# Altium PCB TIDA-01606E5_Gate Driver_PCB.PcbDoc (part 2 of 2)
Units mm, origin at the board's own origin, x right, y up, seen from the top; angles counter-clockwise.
Board outline 135 x 43 mm, 4 copper layers (Top Layer, GND, PWR, Bottom Layer), stack 1.59 mm thick; 184 components, 90 nets, 537 pads, 139 vias.
Unrouted connection lines stored in the file: 48.
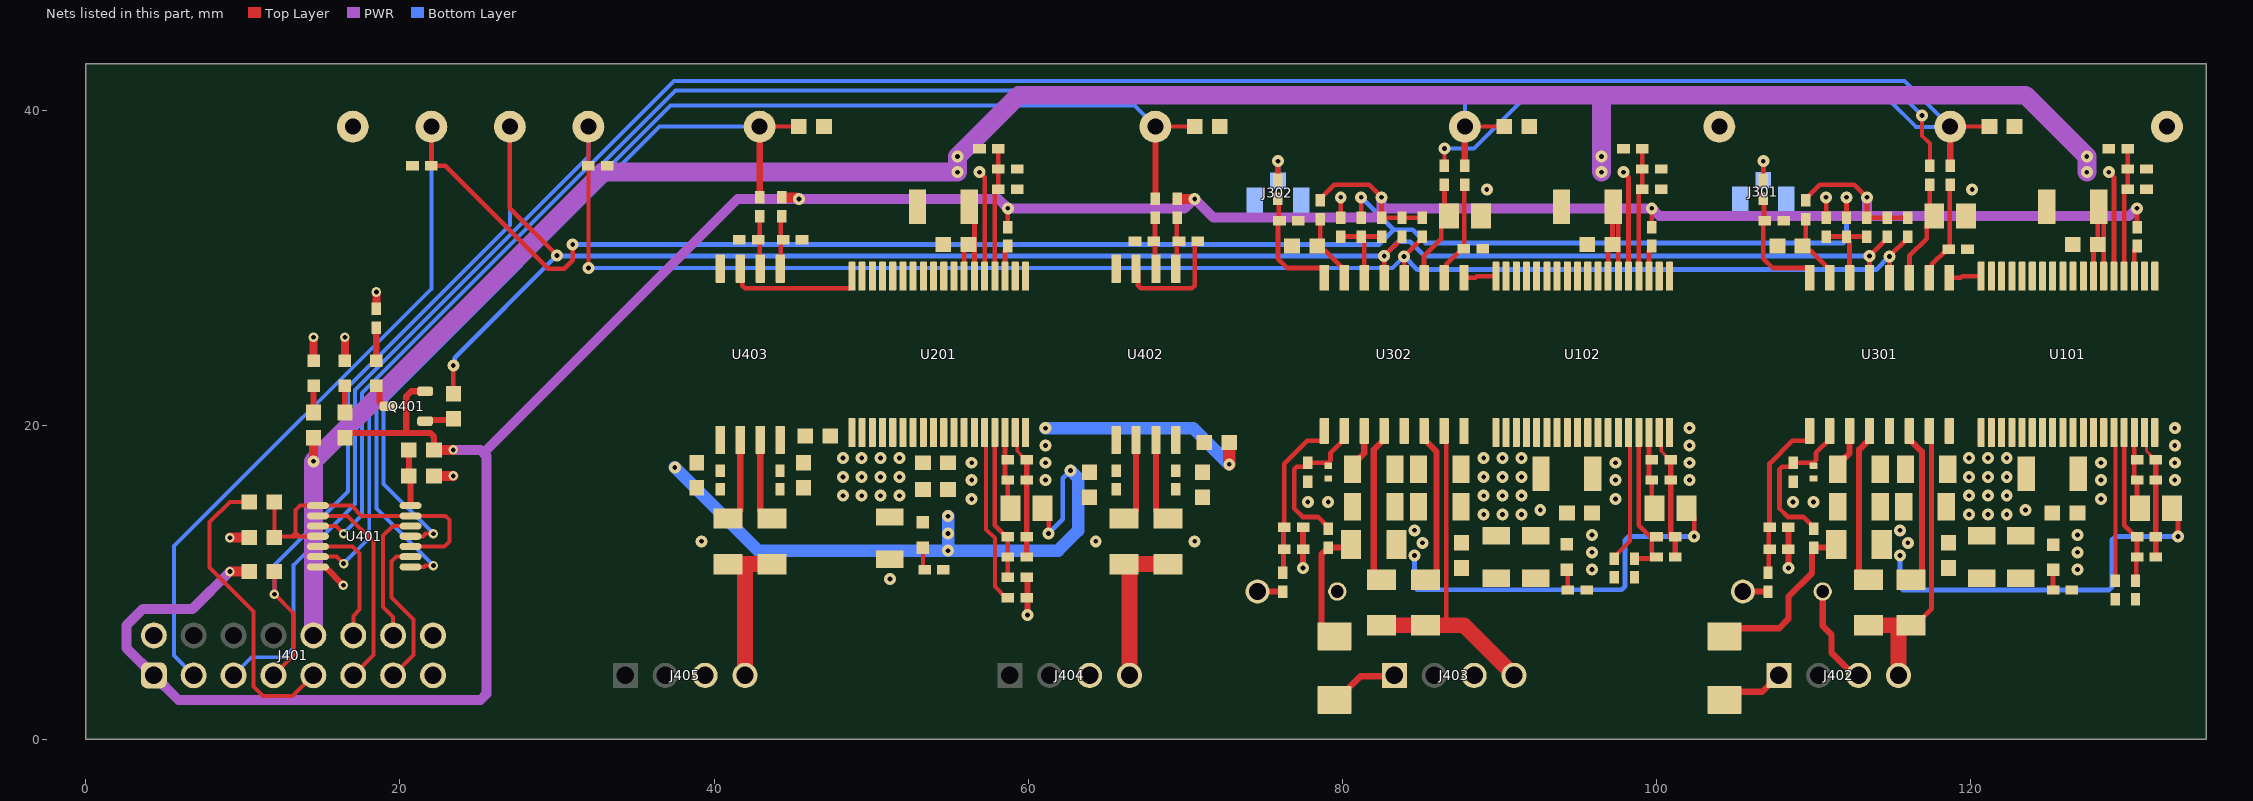
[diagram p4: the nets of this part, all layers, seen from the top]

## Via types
v1: diameter 0.762, hole 0.305, Top Layer to Bottom Layer, tented top, 126 vias
v2: diameter 0.61, hole 0.305, Top Layer to Bottom Layer, tented top, 13 vias

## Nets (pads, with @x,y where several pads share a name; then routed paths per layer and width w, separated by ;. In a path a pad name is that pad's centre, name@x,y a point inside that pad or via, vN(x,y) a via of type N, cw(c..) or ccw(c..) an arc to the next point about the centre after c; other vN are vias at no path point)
+3V3: J401.1 Q401.2 R104.1 R113.1 R204.1 R303.2 R304.2 R305.2 R306.2 R319.2 R320.2 R321.2 R322.2 R402.2 R404.2 R406.1 R413.1 R414.1 | length 203
  Top Layer w0.3: R204.1@58.7,32.6 v1(58.7,33.8) ; R322.2@78.6,34.3 78.6,34.4 79.5,35.3 81.7,35.3 v1(82.5,34.5) R321.2@82.5,33.2 R320.2@83.8,33.2 R319.2@85.1,33.2 ; R113.1@99.7,32.6 v1(99.7,33.8) ; R306.2@109.5,34.3 109.5,34.4 110.4,35.3 112.6,35.3 v1(113.4,34.5) R305.2@113.4,33.2 R304.2@114.7,33.2 R303.2@116,33.2 ; R104.1@130.6,32.6 v1(130.6,33.8)
  Top Layer w0.4: R402.2@16.5,19.2 16.5,19.225 16.775,19.5 20.4,19.5 ; Q401.2@21.6,22.15 20.718,22.15 20.4,21.832 20.4,19.5 ; R406.1@22.168,18.415 22.168,19.266 21.934,19.5 20.4,19.5
  Top Layer w0.635: v2(9.176,10.668) R404.2@10.408,10.668 ; R406.1@22.168,18.415 v2(23.4,18.415) ; R414.1@44.3,34.5 45.266,34.5 45.366,34.4 v1(45.4,34.4) ; R413.1@69.5,34.4 v1(70.6,34.4)
  PWR w0.635: v2(9.176,10.668) 6.808,8.3 3.648,8.3 2.6,7.252 2.6,5.794 J401.1@4.33,4.064 5.894,2.5 25.128,2.5 25.5,2.872 25.5,18.043 25.128,18.415 v2(23.4,18.415) ; 25.314,18.229 41.485,34.4 58.1,34.4 v1(58.7,33.8) 69.966,33.8 70.566,34.4 v1(70.6,34.4) 71.8,33.2 82.128,33.2 82.5,33.572 ; v1(82.5,34.5) 82.5,33.572 ; v1(113.4,34.5) 113.4,33.3 ; v1(130.6,33.8) 130.1,33.3 113.4,33.3 ; 82.5,33.572 82.728,33.8 v1(99.7,33.8) 100.2,33.3 113.4,33.3
+12V: J401.2
+15V_BOT: C109.1 C110.1 C316.2 C317.2 C318.2 C319.2 R110.2 R111.2 R318.2 U102.28 U102.29 U302.5 | length 25
  Top Layer w0.3: R110.2@101.916,14.7 102.4,14.216 v1(102.4,12.9)
  Bottom Layer w0.3: v1(84.6,11.7) 84.6,9.697 84.776,9.521 97.788,9.521 98,9.734 98,12.7 98.2,12.9 v1(102.4,12.9)
  other v1: 95.9,10.8 95.9,11.9 85.1,12.5 95.9,13 84.6,13.3
+15V_MID: C201.1 C202.1 C406.1 C407.1 C408.1 C409.1 R201.2 R202.2 U201.28 U201.29 U402.5 U403.5 | length 41
  Top Layer w0.3: R201.2@60.916,14.7 61.3,14.316 v1(61.3,13.1)
  Bottom Layer w0.3: v1(61.3,13.1) 62.2,14 62.2,16.6 v1(62.7,17.1)
  Bottom Layer w0.8: v1(37.5,17.3) 42.8,12 v1(54.9,12) ; v1(54.9,14.2) v1(54.9,13.1) v1(54.9,12) ; v1(62.7,17.1) 63.175,16.625 63.175,13.275 61.9,12 v1(54.9,12)
+15V_TOP: C101.1 C102.1 C303.2 C304.2 C305.2 C306.2 R101.2 R102.2 R302.2 U101.28 U101.29 U301.5 | length 24.9
  Top Layer w0.3: R101.2@132.816,14.7 133.2,14.316 v1(133.2,12.9)
  Bottom Layer w0.3: v1(115.5,11.7) 115.5,9.676 115.676,9.5 128.824,9.5 129,9.676 129,12.7 129.2,12.9 v1(133.2,12.9)
  other v1: 126.8,10.8 126.8,11.9 116,12.5 126.8,13 115.5,13.3
+24V: C103.1 C104.1 C111.1 C112.1 C203.1 C204.1 J401.10 R105.2 R114.2 R205.2 R403.2 U101.6 U101.7 U102.6 U102.7 U201.6 U201.7 | length 168.4
  Top Layer w0.3: U201.7@55.925,29.475 55.925,31.225 56.063,31.363 56.363,31.363 C204.1@56.575,31.15 ; C203.1@56.2,33.85 56.575,33.475 C204.1@56.575,31.15 ; U201.6@56.575,29.475 C204.1@56.575,31.15 ; U102.7@96.925,29.475 96.925,31.225 C112.1@97.2,31.5 97.2,33.85 C111.1@97.25,33.9 97.575,33.575 U102.6@97.575,29.475 ; U101.7@127.825,29.475 127.825,31.225 C104.1@128.1,31.5 128.1,33.85 128.475,33.475 U101.6@128.475,29.475
  Top Layer w0.6: v1(14.5,17.693) R403.2@14.5,19.2
  PWR w0.6: 14.442,8.052 14.49,8.1
  PWR w1.2: J401.10@14.49,6.604 14.49,8.1 14.49,17.69 32.9,36.1 v1(55.5,36.1) v1(55.5,37.1) 59.4,41 123.5,41 v1(127.4,37.1) v1(127.4,36.1) ; v1(96.5,36.1) v1(96.5,37.1) 96.5,40.9
-4V_BOT: C109.2 C110.2 C113.2 C115.1 C116.1 C314.2 C315.1 C316.1 C317.1 D102.1 R117.1 R118.1 U102.19 U102.20 U102.21 U102.22 U102.23 U102.24 U102.25 U102.26 U102.27 U102.30 U102.31 U102.35 U102.36 U302.8 | length 8.3
  Top Layer w0.2: U102.35@100.175,19.525 100.3,19.4 100.3,18.346 100.6,18.046 100.6,18 100.8,17.8 C115.1@100.9,17.8
  Top Layer w0.35: C116.1@100.9,12.9 R117.1@100.9,16.5 C115.1@100.9,17.8 ; R118.1@101.2,11.6 C116.1@101.2,12.9
  other v1: 89,14.3 90.2,14.3 91.4,14.3 92.6,14.6 97.4,15.3 89,15.5 90.2,15.5 91.4,15.5 97.4,16.5 102.1,16.5 89,16.7 90.2,16.7 91.4,16.7 97.4,17.6 102.1,17.6 89,17.9 90.2,17.9 91.4,17.9 102.1,18.7 102.1,19.8
-4V_Mid: C201.2 C202.2 C205.2 C207.1 C208.1 D201.1 R208.1 R209.1 R421.2 R422.2 U201.19 U201.20 U201.21 U201.22 U201.23 U201.24 U201.25 U201.26 U201.27 U201.30 U201.31 U201.35 U201.36 | length 22.3
  Top Layer w0.2: U201.35@59.175,19.525 59.3,19.4 59.3,18.346 59.6,18.046 59.6,18 59.8,17.8 C207.1@59.9,17.8
  Top Layer w0.35: R209.1@59.9,11.6 C208.1@59.9,12.9 R208.1@59.9,16.5 C207.1@59.9,17.8
  Top Layer w0.8: v1(72.8,17.5) R422.2@72.8,18.9
  Bottom Layer w0.8: v1(61.1,19.8) 70.5,19.8 v1(72.8,17.5)
  other v1: 56.4,15.3 48.2,15.5 49.4,15.5 50.6,15.5 51.8,15.5 56.4,16.5 61.1,16.5 48.2,16.7 49.4,16.7 50.6,16.7 51.8,16.7 56.4,17.6 61.1,17.6 48.2,17.9 49.4,17.9 50.6,17.9 51.8,17.9 61.1,18.7
-4V_TOP: C101.2 C102.2 C105.2 C107.1 C108.1 C301.2 C302.1 C303.1 C304.1 D101.1 R108.1 R109.1 U101.19 U101.20 U101.21 U101.22 U101.23 U101.24 U101.25 U101.26 U101.27 U101.30 U101.31 U101.35 U101.36 U301.8 | length 8.3
  Top Layer w0.2: U101.35@131.075,19.525 131.2,19.4 131.2,18.346 131.5,18.046 131.5,18 131.7,17.8 C107.1@131.8,17.8
  Top Layer w0.35: R109.1@131.8,11.6 C108.1@131.8,12.9 R108.1@131.8,16.5 C107.1@131.8,17.8
  other v1: 119.9,14.3 121.1,14.3 122.3,14.3 123.5,14.6 128.3,15.3 119.9,15.5 121.1,15.5 122.3,15.5 128.3,16.5 133,16.5 119.9,16.7 121.1,16.7 122.3,16.7 128.3,17.6 133,17.6 119.9,17.9 121.1,17.9 122.3,17.9 133,18.7 133,19.8
DESAT_BOT: D302.1 J403.1 | length 4.2
  Top Layer w0.4: D302.1@79.845,2.5 79.845,2.69 81.155,4 83.246,4 J403.1@83.31,4.064
DESAT_TOP: D301.1 J402.1 | length 4.1
  Top Layer w0.4: D301.1@104.325,2.5 104.842,3.017 106.743,3.017 J402.1@107.79,4.064
FLT: FLT401.1 J401.7 R304.1 R320.1 R401.1 R404.1 U301.13 U302.13 | length 155.1
  Top Layer w0.254: J401.7@11.95,4.064 13.24,5.354 13.24,8.001 v2(12.008,9.233) R404.1@12.008,10.668
  Top Layer w0.3: R401.1@23.4,22 v1(23.4,23.8) ; FLT401.1@27,39 27,33.8 v1(30,30.8) ; U302.13@82.665,29.375 v1(82.665,30.765) 83.8,31.9 R320.1@83.8,32 ; U301.13@113.565,29.375 v1(113.565,30.765) 114.7,31.9 R304.1@114.7,32
  Bottom Layer w0.254: v2(12.008,9.233) 12.008,11.087 16.685,15.764 16.685,22.422 27,32.737 FLT401.1@27,39
  Bottom Layer w0.3: v1(23.4,23.8) 23.488,23.888 23.488,24.288 v1(30,30.8) 30.031,30.769 82.661,30.769 v1(82.665,30.765) 83.573,31.673 84.313,31.673 85.221,30.765 v1(113.565,30.765)
GATE_BOT: J403.4 R323.2 R324.2 U302.7 | length 22.2
  Top Layer w0.3: 86.475,7.25 86.616,7.391 86.616,19.484 U302.7@86.475,19.625
  Top Layer w1: R324.2@82.5,7.25 R323.2@85.3,7.25 86.475,7.25 87.744,7.25 J403.4@90.93,4.064
GATE_MID_BOT: J405.4 R418.2 R420.2 | length 9.8
  Top Layer w1: R418.2@40.9,11.15 42.075,11.15 R420.2@43.7,11.15 ; J405.4@41.97,4.064 41.97,11.045
GATE_MID_TOP: J404.4 R416.2 R419.2 | length 10.1
  Top Layer w1: R416.2@66.1,11.15 R416.2@66.185,11.15 ; J404.4@66.45,4.064 66.45,11 66.3,11.15 R416.2@66.185,11.15 ; R419.2@68.9,11.15 R416.2@66.185,11.15
GATE_TOP: J402.4 R307.2 R308.2 U301.7 | length 19.6
  Top Layer w0.3: U301.7@117.375,19.625 117.516,19.484 117.516,8.291 R307.2@116.475,7.25 ; R307.2@116.475,7.25 R307.2@116.2,7.25 R307.2@116.475,7.25
  Top Layer w1: R308.2@113.5,7.25 R307.2@116.275,7.25 ; J402.4@115.41,4.064 115.41,7.1 115.56,7.25 115.675,7.25 R307.2@115.7,7.25
GND: C103.2 C104.2 C106.2 C111.2 C112.2 C114.2 C203.2 C204.2 C206.2 C307.2 C308.2 C309.1 C311.1 C313.2 C320.2 C321.2 C322.2 C323.1 C325.1 C401.2 C402.2 C403.2 C404.2 C405.2 C410.2 C411.2 D402.1 D403.1 J301.2@105.325,34.075 J301.3@108.275,34.075 J302.2@74.425,34.025 J302.3@77.375,34.025 J401.15 J401.16 R107.1 R116.1 R207.1 R405.1 R408.1 R409.1 R410.1 R411.1 R412.1 TP301.1 TP303.1 TP401.1 U101.1 U101.2 U101.5 U101.8 U101.9 U101.10 U101.11 U101.12 U101.13 U101.14 U101.15 U101.16 U101.17 U101.18 U102.1 U102.2 U102.5 U102.8 U102.9 U102.10 U102.11 U102.12 U102.13 U102.14 U102.15 U102.16 U102.17 U102.18 U201.1 U201.2 U201.5 U201.8 U201.9 U201.10 U201.11 U201.12 U201.13 U201.14 U201.15 U201.16 U201.17 U201.18 U301.9 U302.9 U401.7 U402.3 U402.4 U403.3 U403.4 | length 52.4
  Top Layer w0.3: U403.3@41.665,29.95 41.797,29.818 41.797,28.876 41.973,28.7 48.7,28.7 48.775,28.775 U201.18@48.775,29.475 ; v1(56.9,36.1) 57.225,35.775 U201.5@57.225,29.475 ; U402.3@66.865,29.95 66.997,29.818 66.997,28.876 67.173,28.7 70.424,28.7 70.6,28.876 70.6,31.55 70.75,31.7 C404.2@70.8,31.7 ; C322.2@79.9,33.2 v1(79.9,34.5) ; U302.9@87.745,29.375 88.475,29.375 88.575,29.475 U102.18@89.775,29.475 ; v1(97.9,36.1) 98.225,35.775 U102.5@98.225,29.475 ; C308.2@110.8,33.2 v1(110.8,34.5) ; U301.9@118.645,29.375 119.375,29.375 119.475,29.475 U101.18@120.675,29.475 ; v1(128.8,36.1) 129.125,35.775 U101.5@129.125,29.475
  Top Layer w0.381: U401.7@14.776,10.968 15.241,10.968 16.4,9.809 v2(16.4,9.8)
  Top Layer w0.508: D403.1@14.5,24.1 v2(14.5,25.586) ; D402.1@16.5,24.1 v2(16.5,25.586) ; R405.1@18.5,27.4 v2(18.5,28.47)
  Top Layer w0.635: v2(9.176,12.827) R412.1@10.408,12.827 ; C403.2@22.168,16.764 v2(23.4,16.764)
  other v1: 89.2,35 120.1,35
GND_BOT: C113.1 C314.1 C315.2 C318.1 C319.1 C324.1 C326.2 J403.3 R112.2 R115.2 R328.1 R330.1 TP304.2 U302.3 | length 5.4
  Top Layer w0.4: v1(77.5,10.9) C326.2@77.5,12.1 R330.1@77.5,13.5 ; C318.1@80.65,17.2 80.65,17.525 81,17.875 81.07,17.875 81.395,18.2 U302.3@81.395,19.625
  other v1: 77.8,15.1 79.1,15.1
GND_MID: C205.1 C406.2 C407.2 C408.2 C409.2 C412.2 C413.2 C414.2 C415.2 J404.3 J405.3 R203.2 R206.2 | length 2.4
  Top Layer w0.4: v1(59.95,7.9) R206.2@59.95,10.3
  other v1: 51.2,10.2 39.2,12.6 64.3,12.6 70.6,12.6
GND_TOP: C105.1 C301.1 C302.2 C305.1 C306.1 C310.1 C312.2 J402.3 R103.2 R106.2 R312.1 R314.1 TP302.2 U301.3 | length 12.2
  Top Layer w0.4: v1(108.4,10.9) R314.1@108.4,12.1 C312.2@108.4,13.5 ; TP302.2@110.58,9.4 110.58,7.205 111.145,6.641 111.145,5.51 112.87,3.785 J402.3@112.87,3.564 ; C305.1@111.55,17.2 111.55,17.525 111.9,17.875 111.97,17.875 112.295,18.2 U301.3@112.295,19.625
  other v1: 108.7,15.1 110,15.1
NetC106_1: C106.1 R105.1 R107.2 U101.4 | length 8.3
  Top Layer w0.3: U101.4@129.775,29.475 129.775,34.85 129.925,35 C106.1@130,35 R107.2@130,36.3 R105.1@130,37.6
NetC107_2: C107.2 R101.1 R108.2 U101.34 | length 5
  Top Layer w0.3: U101.34@130.425,19.525 130.425,16.65 130.575,16.5 R108.2@130.6,16.5 130.6,14.884 R101.1@130.784,14.7
NetC108_2: C108.2 R106.1 R109.2 U101.33 | length 9.8
  Top Layer w0.3: U101.33@129.775,19.525 129.775,13.625 130.6,12.8 R109.2@130.6,11.6 130.55,11.55 130.55,10.15 R106.1@130.5,10.1
NetC114_1: C114.1 R114.1 R116.2 U102.4 | length 8.3
  Top Layer w0.3: U102.4@98.875,29.475 98.875,34.85 99.025,35 C114.1@99.1,35 R116.2@99.1,36.3 R114.1@99.1,37.6
NetC115_2: C115.2 R110.1 R117.2 U102.34 | length 5
  Top Layer w0.3: U102.34@99.525,19.525 99.525,16.65 99.675,16.5 R117.2@99.7,16.5 99.7,14.884 R110.1@99.884,14.7
NetC116_2: C116.2 R115.1 R118.2 U102.33 | length 9.4
  Top Layer w0.3: R115.1@98.6,11.5 99.6,11.5 99.7,11.6 99.7,12.8 98.875,13.625 U102.33@98.875,19.525
NetC206_1: C206.1 R205.1 R207.2 U201.4 | length 8.3
  Top Layer w0.3: U201.4@57.875,29.475 57.875,34.85 58.025,35 C206.1@58.1,35 R207.2@58.1,36.3 R205.1@58.1,37.6
NetC207_2: C207.2 R201.1 R208.2 U201.34 | length 5
  Top Layer w0.3: U201.34@58.525,19.525 58.525,17.35 58.525,16.65 58.675,16.5 R208.2@58.7,16.5 58.7,14.884 R201.1@58.884,14.7
NetC208_2: C208.2 R206.1 R209.2 U201.33 | length 9.6
  Top Layer w0.3: U201.33@57.875,19.525 57.875,13.625 58.7,12.8 R209.2@58.7,11.6 R206.1@58.7,10.3
NetC307_1: C307.1 R301.2 U301.10 | length 6.5
  Top Layer w0.3: U301.10@117.375,29.375 117.525,29.525 117.525,30.225 118.5,31.2 C307.1@118.6,31.2 118.669,31.269 118.669,35.269 R301.2@118.7,35.3
NetC308_1: C308.1 R305.1 R310.2 U301.14 | length 5.3
  Top Layer w0.3: C308.1@110.8,32 R305.1@113.4,32 ; R310.2@112.1,32 112.1,31.9 112.295,31.705 U301.14@112.295,29.375
NetC309_2: C309.2 R306.1 U301.15 | length 4.7
  Top Layer w0.3: R306.1@109.5,33.1 109.5,31.6 C309.2@109.3,31.4 109.625,31.075 109.85,31.075 111.025,29.9 U301.15@111.025,29.375
NetC310_2: C310.2 R309.1 R312.2 U301.2 | length 10.1
  Top Layer w0.3: R309.1@110,13.4 110,13.5 109.35,14.15 108.369,14.15 107.833,14.686 107.833,17.174 108.008,17.35 108.55,17.35 108.7,17.5 R312.2@108.7,17.6 110,17.6 110.15,17.75 110.15,18.225 111.025,19.1 U301.2@111.025,19.625
NetC311_2: C311.2 R311.2 U301.16 | length 7.6
  Top Layer w0.3: R311.2@106.8,34.4 106.85,34.35 106.85,33.05 C311.2@106.9,33 106.8,32.9 106.8,30.6 107.401,29.999 109.605,29.999 109.755,29.849 U301.16@109.755,29.375
NetC312_1: C312.1 R313.1 R314.2 U301.1 | length 10.7
  Top Layer w0.3: R313.1@107.1,10.6 107.15,10.65 107.15,13.45 C312.1@107.2,13.5 107.2,17.55 108.651,19.001 109.605,19.001 109.755,19.151 U301.1@109.755,19.625
NetC313_1: C313.1 R316.2 U301.11 | length 6.7
  Top Layer w0.3: U301.11@116.105,29.375 116.105,30.765 117.199,31.859 117.199,32.815 C313.1@117.684,33.3 117.4,33.584 R316.2@117.4,35.3
NetC320_1: C320.1 R317.1 U302.10 | length 6.5
  Top Layer w0.3: U302.10@86.475,29.375 86.625,29.525 86.625,30.225 87.6,31.2 87.7,31.2 87.769,31.269 87.769,35.269 R317.1@87.8,35.3
NetC321_1: C321.1 R315.1 U302.11 | length 6.7
  Top Layer w0.3: U302.11@85.205,29.375 85.205,30.765 86.299,31.859 86.299,32.815 C321.1@86.784,33.3 86.5,33.584 R315.1@86.5,35.3
NetC322_1: C322.1 R321.1 R326.2 U302.14 | length 5.3
  Top Layer w0.3: C322.1@79.9,32 R321.1@82.5,32 ; R326.2@81.2,32 81.2,31.9 81.395,31.705 U302.14@81.395,29.375
NetC323_2: C323.2 R322.1 U302.15 | length 4.7
  Top Layer w0.3: R322.1@78.6,33.1 78.6,31.6 C323.2@78.4,31.4 78.725,31.075 78.95,31.075 80.125,29.9 U302.15@80.125,29.375
NetC324_2: C324.2 R325.1 R328.2 U302.2 | length 10.1
  Top Layer w0.3: R325.1@79.1,13.4 79.1,13.5 78.45,14.15 77.469,14.15 76.933,14.686 76.933,17.174 77.108,17.35 77.65,17.35 77.8,17.5 R328.2@77.8,17.6 79.1,17.6 79.25,17.75 79.25,18.225 80.125,19.1 U302.2@80.125,19.625
NetC325_2: C325.2 R327.2 U302.16 | length 7.6
  Top Layer w0.3: R327.2@75.9,34.4 75.95,34.35 75.95,33.05 C325.2@76,33 75.9,32.9 75.9,30.6 76.501,29.999 78.705,29.999 78.855,29.849 U302.16@78.855,29.375
NetC326_1: C326.1 R329.1 R330.2 U302.1 | length 10.7
  Top Layer w0.3: R329.1@76.2,10.6 76.25,10.65 76.25,13.45 R330.2@76.3,13.5 76.3,17.55 77.751,19.001 78.705,19.001 78.855,19.151 U302.1@78.855,19.625
NetC403_1: C403.1 R406.2 U401.14 | length 3.4
  Top Layer w0.381: C403.1@20.568,16.764 R406.2@20.568,18.415 ; U401.14@20.676,14.868 C403.1@20.676,16.656
NetC404_1: C404.1 R413.2 U402.1 | length 3.3
  Top Layer w0.3: U402.1@69.405,29.95 69.453,29.997 69.453,33.152 R413.2@69.5,33.2
NetC405_1: C405.1 R414.2 U403.1 | length 3.4
  Top Layer w0.3: U403.1@44.205,29.95 44.252,29.997 44.252,33.252 R414.2@44.3,33.3
NetC410_1: C410.1 R417.2 U403.2 | length 3.4
  Top Layer w0.3: R417.2@42.9,33.3 42.918,33.282 42.918,29.967 U403.2@42.935,29.95
NetC411_1: C411.1 R415.2 U402.2 | length 3.3
  Top Layer w0.3: R415.2@68,33.2 68.067,33.133 68.067,31.705 68.067,30.017 U402.2@68.135,29.95
NetC412_1: C412.1 C413.1 R421.1 U403.8
NetC414_1: C414.1 C415.1 R422.1 U402.8
NetD101_2: D101.2 R102.1 | length 1.3
  Top Layer w0.3: R102.1@125.25,9.5 D101.2@125.249,10.775
NetD102_2: D102.2 R111.1 | length 1.3
  Top Layer w0.3: R111.1@94.35,9.5 D102.2@94.349,10.775
NetD201_2: D201.2 R202.1 | length 1.4
  Top Layer w0.254: D201.2@53.299,12.2 53.299,10.901 R202.1@53.4,10.8
NetD301_2: D301.2 R302.1 R309.2 | length 11.4
  Top Layer w0.4: D301.2@104.325,6.55 104.847,7.072 107.822,7.072 108.4,7.65 108.4,9.074 109.9,10.574 109.9,12.1 R309.2@110,12.2 111.35,12.2 R302.1@111.55,12.4
NetD302_2: D302.2 R318.1 R325.2 | length 7.9
  Top Layer w0.4: D302.2@79.5,6.55 79.365,6.55 78.675,7.24 78.675,11.766 78.909,12 79,12 79.1,12.1 R325.2@79.1,12.2 80.45,12.2 R318.1@80.65,12.4
NetD401_1: D401.1 R405.2 | length 2.1
  Top Layer w0.4: D401.1@18.5,24.1 R405.2@18.5,26.2
NetD401_2: D401.2 Q401.3 | length 1.7
  Top Layer w0.254: D401.2@18.481,22.481 D401.2@18.5,22.5
  Top Layer w0.4: D401.2@18.5,22.5 18.7,22.3 18.7,21.5 19,21.2 Q401.3@19.2,21.2
NetD402_2: D402.2 R402.1 | length 1.7
  Top Layer w0.4: R402.1@16.5,20.8 D402.2@16.5,22.5
NetD403_2: D403.2 R403.1 | length 1.7
  Top Layer w0.4: R403.1@14.5,20.8 D403.2@14.5,22.5
NetJ301_1: J301.1 R311.1 | length 2.4
  Top Layer w0.3: R311.1@106.8,35.6 v1(106.8,36.8)
  Bottom Layer w0.3: J301.1@106.8,35.6 v1(106.8,36.8)
NetJ302_1: J302.1 R327.1 | length 2.5
  Top Layer w0.3: R327.1@75.9,35.6 v1(75.9,36.8)
  Bottom Layer w0.3: J302.1@75.9,35.55 v1(75.9,36.8)
NetQ401_1: Q401.1 R401.2 | length 1.9
  Top Layer w0.4: Q401.1@21.6,20.25 21.675,20.325 23.325,20.325 R401.2@23.4,20.4
NetR103_1: R103.1 U101.32 | length 9.5
  Top Layer w0.254: U101.32@129.125,19.525 129.125,18.825 129.223,18.727 R103.1@129.223,10.077
NetR104_2: R104.2 U101.3 | length 2
  Top Layer w0.3: U101.3@130.425,29.475 130.425,31.125 130.6,31.3 R104.2@130.6,31.4
NetR112_1: R112.1 U102.32 | length 8.5
  Top Layer w0.254: R112.1@97.3,11.5 97.3,11.6 98.323,12.623 98.323,19.427 U102.32@98.225,19.525
  Top Layer w0.3: R112.1@97.3,11.45 R112.1@97.3,11.5
NetR113_2: R113.2 U102.3 | length 2
  Top Layer w0.3: U102.3@99.525,29.475 99.525,31.125 99.7,31.3 R113.2@99.7,31.4
NetR203_1: R203.1 U201.32 | length 11.2
  Top Layer w0.254: U201.32@57.225,19.525 57.323,19.427 57.323,13.36 57.875,12.808 57.875,9.725 R203.1@58.6,9
  Top Layer w0.3: R203.1@58.65,9 R203.1@58.75,9
NetR204_2: R204.2 U201.3 | length 2
  Top Layer w0.3: U201.3@58.525,29.475 58.525,31.125 58.7,31.3 R204.2@58.7,31.4
NetR307_1: R307.1 U301.6 | length 10.2
  Top Layer w0.4: U301.6@116.105,19.625 116.105,19.1 116.9,18.305 116.9,10.6 116.45,10.15 R307.1@116.2,10.15
NetR308_1: R308.1 U301.4 | length 9.8
  Top Layer w0.4: R308.1@112.9,10.15 112.9,18.435 113.565,19.1 U301.4@113.565,19.625
NetR313_2: R313.2 TP302.1 | length 1.8
  Top Layer w0.4: TP302.1@105.5,9.4 R313.2@107.1,9.4 107.1,9.3 R313.2@107,9.2
NetR323_1: R323.1 U302.6 | length 10.2
  Top Layer w0.4: U302.6@85.205,19.625 85.205,19.1 86,18.305 86,10.6 85.55,10.15 R323.1@85.3,10.15
NetR324_1: R324.1 U302.4 | length 9.8
  Top Layer w0.4: R324.1@82,10.15 82,18.435 82.665,19.1 U302.4@82.665,19.625
NetR329_2: R329.2 TP304.1 | length 2.1
  Top Layer w0.4: TP304.1@74.321,9.3 74.421,9.4 TP304.1@74.6,9.4 ; TP304.1@74.679,9.4 R329.2@76.2,9.4 76.2,9.3 R329.2@76.1,9.2
NetR407_2: R407.2 R412.2 U401.1 U401.4 U401.10 U401.13 | length 21.5
  Top Layer w0.254: R407.2@12.008,15.113 R412.2@12.008,12.827 12.099,12.918 13.113,12.918 ; U401.4@14.776,12.918 13.621,12.918 ; U401.10@20.676,12.268 22.841,12.268 23.146,12.573 23.146,13.97 22.898,14.218 U401.13@20.676,14.218 17.564,14.218 16.914,14.868 U401.1@14.776,14.868 13.63,14.868 13.367,14.605 13.367,13.172 ; 13.113,12.918 13.621,12.918 ; 13.113,12.918 13.367,13.172 ; 13.367,13.172 13.621,12.918
NetR416_1: R416.1 U402.6 | length 5.5
  Top Layer w0.4: R416.1@66.1,14.05 66.375,14.05 66.865,14.54 U402.6@66.865,19.05
NetR418_1: R418.1 U403.6 | length 5.5
  Top Layer w0.4: R418.1@40.9,14.05 41.175,14.05 41.665,14.54 U403.6@41.665,19.05
NetR419_1: R419.1 U402.7 | length 5.5
  Top Layer w0.4: U402.7@68.135,19.05 68.135,14.54 68.625,14.05 R419.1@68.9,14.05
NetR420_1: R420.1 U403.7 | length 5.5
  Top Layer w0.4: U403.7@42.935,19.05 42.935,14.54 43.425,14.05 R420.1@43.7,14.05
PWM1: J401.11 U401.2 | length 13.3
  Top Layer w0.254: U401.2@14.776,14.218 16.675,14.218 18.32,12.573 18.32,5.354 J401.11@17.03,4.064
PWM1_B: PWM401.1 R301.1 R315.2 R411.2 U401.3 | length 162.1
  Top Layer w0.254: U401.3@14.776,13.568 15.928,13.568 v2(16.415,13.081) ; R315.2@86.5,36.5 v1(86.5,37.6) ; PWM401.1@118.7,39 R411.2@121.2,39
  Top Layer w0.4: R301.1@118.7,36.5 PWM401.1@118.7,39
  Bottom Layer w0.254: v2(16.415,13.081) 17.593,14.259 17.593,22.034 37.459,41.9 115.8,41.9 PWM401.1@118.7,39 118.665,38.965 116.538,38.965 114.85,40.653 91.428,40.653 88.375,37.6 v1(86.5,37.6)
PWM2: J401.12 U401.5 | length 8.2
  Top Layer w0.254: U401.5@14.776,12.268 16.974,12.268 17.431,11.811 17.431,8.255 17.03,7.854 J401.12@17.03,6.604
PWM2_B: PWM402.1 R316.1 R317.2 R410.2 U401.6 | length 131.4
  Top Layer w0.254: U401.6@14.776,11.618 15.973,11.618 v2(16.415,11.176) ; PWM402.1@87.8,39 R410.2@90.3,39 ; v1(116.9,39.7) 116.9,38.418 117.4,37.918 R316.1@117.4,36.5
  Top Layer w0.4: R317.2@87.8,36.5 PWM402.1@87.8,39
  Bottom Layer w0.254: v2(16.415,11.176) 18.047,12.808 18.047,21.809 37.538,41.3 87.8,41.3 ; PWM402.1@87.8,39 87.8,41.3 ; v1(116.9,39.7) 115.3,41.3 87.8,41.3
PWM3: J401.13 U401.9 | length 9.7
  Top Layer w0.254: J401.13@19.57,4.064 20.86,5.354 20.86,7.62 19.463,9.017 19.463,11.303 19.778,11.618 U401.9@20.676,11.618
PWM3_B: PWM403.1 R409.2 R415.1 U401.8 | length 78.6
  Top Layer w0.254: U401.8@20.676,10.968 21.541,10.968 21.622,11.049 v2(22.13,11.049) ; PWM403.1@68.1,39 R409.2@70.6,39
  Top Layer w0.4: R415.1@68.1,34.4 PWM403.1@68.1,39
  Bottom Layer w0.254: v2(22.13,11.049) 18.501,14.678 18.501,21.621 37.223,40.343 66.757,40.343 PWM403.1@68.1,39
PWM4: J401.14 U401.12 | length 8.6
  Top Layer w0.254: J401.14@19.57,6.604 19.57,7.767 18.934,8.403 18.934,12.954 19.548,13.568 U401.12@20.676,13.568
PWM4_B: PWM404.1 R408.2 R417.1 U401.11 | length 49.4
  Top Layer w0.254: U401.11@20.676,12.918 21.459,12.918 21.622,13.081 v2(22.13,13.081) ; PWM404.1@42.9,39 R408.2@45.4,39
  Top Layer w0.4: R417.1@42.9,34.5 PWM404.1@42.9,39
  Bottom Layer w0.254: v2(22.13,13.081) 18.955,16.256 18.955,21.415 36.54,39 PWM404.1@42.9,39
PWM_EN: J401.9 R407.1 | length 19.3
  Top Layer w0.254: R407.1@10.408,15.113 9.173,15.113 7.878,13.818 7.878,10.922 10.672,8.128 10.672,3.353 11.281,2.743 13.169,2.743 J401.9@14.49,4.064
RDY: C401.1 J401.5 R303.1 R319.1 RDY401.1 U301.12 U302.12 | length 144.5
  Top Layer w0.254: v1(32,30) C401.1@32,36.5 RDY401.1@32,39
  Top Layer w0.3: U302.12@83.935,29.375 v1(83.935,30.735) 85.1,31.9 R319.1@85.1,32 ; U301.12@114.835,29.375 v1(114.835,30.735) 116,31.9 R303.1@116,32
  Bottom Layer w0.254: J401.5@9.41,4.064 10.562,5.216 12.614,5.216 13.24,5.842 13.24,11.077 17.139,14.976 17.139,22.222 32,37.083 RDY401.1@32,39 ; v1(32,30) 83.2,30 v1(83.935,30.735)
  Bottom Layer w0.3: v1(83.935,30.735) 84.77,29.9 114,29.9 v1(114.835,30.735)
RST: C402.1 J401.3 R310.1 R326.1 RST401.1 | length 147.8
  Top Layer w0.254: C402.1@22,36.5 RST401.1@22,39
  Top Layer w0.3: C402.1@22,36.5 22.9,36.5 29.45,29.95 30.45,29.95 31,30.5 v1(31,31.5) ; R326.1@81.2,33.2 v1(81.2,34.5) ; R310.1@112.1,33.2 v1(112.1,34.5)
  Bottom Layer w0.254: J401.3@6.87,4.064 5.62,5.314 5.62,12.296 22,28.676 RST401.1@22,39
  Bottom Layer w0.3: v1(31,31.5) 82.35,31.5 83.275,32.425 ; v1(81.2,34.5) 83.275,32.425 ; v1(112.1,34.5) 112.1,31.771 111.924,31.595 85.299,31.595 84.469,32.425 83.275,32.425
pads on no net: J301.2@105.3,34.075 J301.3@108.3,34.075 J302.2@74.4,34.025 J302.3@77.4,34.025 J401.4 J401.6 J401.8 J402.2 J403.2 J404.1 J404.2 J405.1 J405.2

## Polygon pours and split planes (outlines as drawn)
GND_TOP on Top Layer "TOP_LAYER_GND_TOP_P046" (solid, remove dead copper, pour order 46): 112,2 112,4.5 114.974,4.5 114.974,11.7 127.6,11.7 127.6,9.15 131,9.15 131,8.27 124.73,2
GND on Top Layer "TOP_LAYER_GND_P042" (solid, remove dead copper, pour order 42): 0.5,0.5 26,0.5 26,18.5 36,28.5 134.5,28.5 134.5,42.5 0.5,42.5
+24V on Top Layer "TOP_LAYER_+24V_P041" (solid, remove dead copper, pour order 41): 127.6,28.5 128.7,28.5 128.7,36 129.4,36.7 129.4,38.3 127.7,38.3 126.7,37.3 126.7,32.875 127.6,31.975
+24V on Top Layer "TOP_LAYER_+24V_P040" (solid, remove dead copper, pour order 40): 96.7,28.5 97.8,28.5 97.8,36 98.5,36.7 98.5,38.3 96.8,38.3 95.8,37.3 95.8,32.875 96.7,31.975
+24V on Top Layer "TOP_LAYER_+24V_P039" (solid, remove dead copper, pour order 39): 55.7,28.5 56.8,28.5 56.8,36 57.5,36.7 57.5,38.3 55.8,38.3 54.8,37.3 54.8,32.875 55.7,31.975
NetC412_1 on Top Layer "TOP_LAYER_NETC412_1_P033" (solid, remove dead copper, pour order 33): 43.9,20.5 46.4,20.5 46.4,16.7 43.9,16.7
GND_MID on Top Layer "TOP_LAYER_GND_MID_P032" (solid, remove dead copper, pour order 32): 37,16.8 37,4.064 41.97,4.064 41.97,12.3 45.1,12.3 52,5.4 62.7,5.4 62.7,3 65.1,3 65.1,5.4 66.45,5.4 66.45,12.077 71.8,12.077 71.8,16.8
NetC414_1 on Top Layer "TOP_LAYER_NETC414_1_P031" (solid, remove dead copper, pour order 31): 69.1,20.5 71.7,20.5 71.7,16.5 69.1,16.5
+15V_MID on Top Layer "TOP_LAYER_+15V_MID_P030" (solid, remove dead copper, pour order 30): 65.9,20.5 65.9,16.5 62.2,16.5 62.2,17.5 65.2,20.5
+15V_MID on Top Layer "TOP_LAYER_+15V_MID_P029" (solid, remove dead copper, pour order 29): 40.7,20.5 40.7,16.8 37,16.8 37,17.5 40,20.5
-4V_Mid on Top Layer "TOP_LAYER_-4V_MID_P028" (solid, remove dead copper, pour order 28): 54.4,20.5 46.9,20.5 46.9,15.9 49.412,13.388 54.4,13.36
-4V_Mid on Top Layer "TOP_LAYER_-4V_MID_P027" (solid, remove dead copper, pour order 27): 61.6,20.5 61.6,16.028 59.6,16.028 55.6,16.028 55.6,20.5
+15V_MID on Top Layer "TOP_LAYER_+15V_MID_P026" (solid, remove dead copper, pour order 26): 54.3,20.5 55.497,20.5 55.497,10.5 54.3,10.5
GND_BOT on Top Layer "TOP_LAYER_GND_BOT_P018" (solid, remove dead copper, pour order 18): 87.52,2 87.52,3.9 88.12,4.5 90.494,4.5 86.616,8.378 86.616,11.7 99.121,11.7 99.121,9.221 91.9,2
-4V_BOT on Top Layer "TOP_LAYER_-4V_BOT_P017" (solid, remove dead copper, pour order 17): 103.6,20.5 103.6,16.028 100.6,16.028 96.6,16.028 96.6,20.5
-4V_BOT on Top Layer "TOP_LAYER_-4V_BOT_P016" (solid, remove dead copper, pour order 16): 95.4,20.5 86.784,20.5 86.784,11.9 95.4,11.9
GND_BOT on Top Layer "TOP_LAYER_GND_BOT_P015" (solid, remove dead copper, pour order 15): 82.665,19.1 82.665,20.5 79.945,20.5 79.945,18.914 78.581,17.55 77.308,17.55 76.933,17.174 76.933,14.686 77.35,14.268 78.332,14.268 78.775,13.825 82,13.825 82,18.435
+15V_BOT on Top Layer "TOP_LAYER_+15V_BOT_P014" (solid, remove dead copper, pour order 14): 85.205,20.5 85.205,19.1 86,18.305 86,11.1 82,11.1 82,18.435 82.665,19.1 82.665,20.5
+15V_BOT on Top Layer "TOP_LAYER_+15V_BOT_P013" (solid, remove dead copper, pour order 13): 95.3,20.5 96.497,20.5 96.497,9.195 95.3,9.195
-4V_TOP on Top Layer "TOP_LAYER_-4V_TOP_P005" (solid, remove dead copper, pour order 5): 134.5,20.5 134.5,16 127.5,16 127.5,20.5
-4V_TOP on Top Layer "TOP_LAYER_-4V_TOP_P003" (solid, remove dead copper, pour order 3): 126.3,20.5 117.684,20.5 117.684,11.9 126.3,11.9
GND_TOP on Top Layer "TOP_LAYER_GND_TOP_P002" (solid, remove dead copper, pour order 2): 113.565,19.1 113.565,20.5 110.845,20.5 110.845,18.914 109.481,17.55 108.208,17.55 107.833,17.174 107.833,14.686 108.25,14.268 109.232,14.268 109.675,13.825 112.9,13.825 112.9,18.435
+15V_TOP on Top Layer "TOP_LAYER_+15V_TOP_P001" (solid, remove dead copper, pour order 1): 126.2,20.5 127.397,20.5 127.397,9.195 126.2,9.195
+15V_TOP on Top Layer "TOP_LAYER_+15V_TOP_P000" (solid, remove dead copper, pour order 0): 116.105,20.5 116.105,19.1 116.9,18.305 116.9,11.1 112.9,11.1 112.9,18.435 113.565,19.1 113.565,20.5
GND_TOP on GND "GND_GND_TOP_P047" (solid, remove dead copper, pour order 47): 111.891,2 111.891,4.425 110.926,5.39 110.926,6.51 110.468,6.968 106.962,6.929 106.962,20.5 132.037,20.5 132.037,9.37 124.667,2
GND on GND "GND_GND_P043" (solid, remove dead copper, pour order 43): 0.5,0.5 26,0.5 26,18.5 36,28.5 134.5,28.5 134.5,42.5 0.5,42.5
GND_MID on GND "GND_GND_MID_P036" (solid, remove dead copper, pour order 36): 40,20.5 37,17.5 37,4.064 38.2,4.064 38.2,2.9 40.6,2.9 40.6,4.064 41.97,5.4 61.37,5.4 62.7,4.064 62.7,2.9 65.1,2.9 65.1,4.064 65.55,4.95 71.8,11.2 71.8,20.5
GND_BOT on GND "GND_GND_BOT_P019" (solid, remove dead copper, pour order 19): 102.3,12.4 91.9,2 87.411,2 87.411,4.425 84.636,7.2 75.973,7.2 75.973,20.5 102.3,20.5
GND_MID on Bottom Layer "BOTTOM_LAYER_GND_MID_P051" (solid, remove dead copper, pour order 51): 40,20.5 37,17.5 37,4.064 38.2,4.064 38.2,2.9 40.6,2.9 40.6,4.064 41.97,5.4 61.37,5.4 62.7,4.064 62.7,2.9 65.1,2.9 65.1,4.064 65.55,4.95 71.8,11.2 71.8,20.5
GND_TOP on Bottom Layer "BOTTOM_LAYER_GND_TOP_P049" (solid, remove dead copper, pour order 49): 111.891,2 111.891,4.425 110.926,5.39 110.926,6.51 110.468,6.968 106.962,6.929 106.962,20.5 132.037,20.5 132.037,9.37 124.667,2
GND on Bottom Layer "BOTTOM_LAYER_GND_P045" (solid, remove dead copper, pour order 45): 0.5,0.5 26,0.5 26,18.5 36,28.5 134.5,28.5 134.5,42.5 0.5,42.5
-4V_Mid on Bottom Layer "BOTTOM_LAYER_-4V_MID_P034" (solid, remove dead copper, pour order 34): 37,17.5 42.2,12.3 62.7,12.4 62.7,20.5 40,20.5
GND_BOT on Bottom Layer "BOTTOM_LAYER_GND_BOT_P025" (solid, remove dead copper, pour order 25): 102.3,12.4 91.9,2 87.411,2 87.411,4.425 84.636,7.2 75.973,7.2 75.973,20.5 102.3,20.5
+15V_BOT on Bottom Layer "BOTTOM_LAYER_+15V_BOT_P023" (solid, remove dead copper, pour order 23): 97.6,10 83.003,10 83,10.003 83,20.5 97.6,20.5
-4V_BOT on Bottom Layer "BOTTOM_LAYER_-4V_BOT_P022" (solid, remove dead copper, pour order 22): 86.1,13.8 103.6,13.8 103.6,20.5 86.1,20.5
+15V_TOP on Bottom Layer "BOTTOM_LAYER_+15V_TOP_P010" (solid, remove dead copper, pour order 10): 128.5,10 113.903,10 113.9,10.003 113.9,20.5 128.5,20.5
-4V_TOP on Bottom Layer "BOTTOM_LAYER_-4V_TOP_P007" (solid, remove dead copper, pour order 7): 117,13.8 134.5,13.8 134.5,20.5 117,20.5
GND_MID on PWR "PWR_GND_MID_P050" (solid, remove dead copper, pour order 50): 40,20.5 37,17.5 37,4.064 38.2,4.064 38.2,2.9 40.6,2.9 40.6,4.064 41.97,5.4 61.37,5.4 62.7,4.064 62.7,2.9 65.1,2.9 65.1,4.064 65.55,4.95 71.8,11.2 71.8,20.5
GND_TOP on PWR "PWR_GND_TOP_P048" (solid, remove dead copper, pour order 48): 111.891,2 111.891,4.425 110.926,5.39 110.926,6.51 110.468,6.968 106.962,6.929 106.962,20.5 132.037,20.5 132.037,9.37 124.667,2
GND on PWR "PWR_GND_P044" (solid, remove dead copper, pour order 44): 0.5,0.5 26,0.5 26,17.9 36.6,28.5 134.5,28.5 134.5,42.5 0.5,42.5
-4V_Mid on PWR "PWR_-4V_MID_P037" (solid, remove dead copper, pour order 37): 37,17.5 42.5,12 62.7,12 62.7,20.5 40,20.5
GND_BOT on PWR "PWR_GND_BOT_P024" (solid, remove dead copper, pour order 24): 102.3,12.4 91.9,2 87.411,2 87.411,4.425 84.636,7.2 75.973,7.2 75.973,20.5 102.3,20.5
+15V_BOT on PWR "PWR_+15V_BOT_P021" (solid, remove dead copper, pour order 21): 97.6,10 83.003,10 83,10.003 83,20.5 97.6,20.5
-4V_BOT on PWR "PWR_-4V_BOT_P020" (solid, remove dead copper, pour order 20): 86.1,13.8 103.6,13.8 103.6,20.5 86.1,20.5
+15V_TOP on PWR "PWR_+15V_TOP_P009" (solid, remove dead copper, pour order 9): 128.5,10 113.903,10 113.9,10.003 113.9,20.5 128.5,20.5
-4V_TOP on PWR "PWR_-4V_TOP_P008" (solid, remove dead copper, pour order 8): 117,13.8 134.5,13.8 134.5,20.5 117,20.5

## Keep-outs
Keep-Out Layer:
  text ".Layer_Name" at 11.306,-30.061 h1.52

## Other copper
Top Layer:
  region net -4V_Mid: 56,18.3 55.7,18.6 55.7,20.5 56.8,20.5 56.8,13.2 57.4,12.6 57.4,10.5 56,10.5
  region net -4V_Mid: 53.3,20.5 54.2,20.5 54.2,18.6 53.3,17.7
  region net +15V_MID: 54.4,20.5 55.5,20.5 55.5,17.875 54.4,17.875
  region net GND_BOT: 77.411,14.944 77.652,14.703 79.1,14.703 79.1,15.606 78.256,16.45 77.411,16.45
  region net -4V_TOP: 131.2,18.35 131.55,18 131.55,18.872 131.508,18.914 131.467,18.873 131.2,18.873
  region net +15V_BOT: 95.4,20.5 96.5,20.5 96.5,17.875 95.4,17.875
  region net -4V_BOT: 94.3,20.5 95.2,20.5 95.2,18.6 94.3,17.7
  region net -4V_BOT: 97,18.3 96.7,18.6 96.7,20.5 97.8,20.5 97.8,15.1 97.6,14.9 97.2,14.9 97,15.1
  pour cut-out: 102.467,6.968 110.468,6.968 110.926,6.51 110.926,5.39 111.891,4.425 111.891,1.253 111.408,0.77 103.077,0.77 102.467,1.38
  region net -4V_TOP: 127.9,18.3 127.6,18.6 127.6,20.5 128.7,20.5 128.7,15.1 128.5,14.9 128.1,14.9 127.9,15.1
  region net -4V_TOP: 125.2,20.5 126.1,20.5 126.1,18.6 125.2,17.7
  region net GND_TOP: 108.311,14.944 108.552,14.703 110,14.703 110,15.606 109.156,16.45 108.311,16.45
  region net +15V_TOP: 126.3,20.5 127.4,20.5 127.4,17.875 126.3,17.875
  text ".Layer_Name" at 11.306,-30.061 h1.52
PWR:
  text "'.Layer_Name'" at 11.43,-30.124 h1.52
GND:
  pour cut-out: 102.467,6.968 110.468,6.968 110.926,6.51 110.926,5.39 111.891,4.425 111.891,1.253 111.408,0.77 103.077,0.77 102.467,1.38
  text "'.Layer_Name'" at 11.379,-30.048 h1.52
Bottom Layer:
  text ".Layer_Name" at 11.306,-30.061 h1.52

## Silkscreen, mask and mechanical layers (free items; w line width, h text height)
Top Overlay:
  circle w0.254: c109.755,21.3 r0.114
  circle w0.254: c78.855,21.3 r0.114
  text "'.PRJ_Number'.PCB_Rev" at 1.9,32.7 h2.75
  text ".Layer_Name" at 11.306,-30.061 h1.52
Bottom Overlay:
  text ".Layer_Name" at 11.306,-30.061 h1.52
Top Paste:
  text ".Layer_Name" at 11.306,-30.061 h1.52
Bottom Paste:
  text ".Layer_Name" at 11.306,-30.061 h1.52
Top Solder:
  text ".Layer_Name" at 11.306,-30.061 h1.52
  text ".Layer_Name" at 11.306,-30.061 h1.52
Bottom Solder:
  text ".Layer_Name" at 11.306,-30.061 h1.52
Drill Guide:
  text ".Layer_Name" at 11.306,-30.061 h1.52
M1 Board Outline:
  the board outline again, w0.254
M2 Board Dimensions:
  rectangle: -0.175,-18.415 9.35,-15.24
  rectangle: -3.35,-15.24 -0.175,-12.065
  lines w0.178: -3.35,-15.24 22.05,-15.24 ; -0.175,-18.415 -0.175,-12.065 ; 3,-18.415 3,-12.065 ; 9.35,-18.415 9.35,-12.065 ; 15.7,-18.415 15.7,-12.065 ; -3.35,-18.415 -3.35,-12.065 22.05,-12.065 22.05,-18.415 -3.35,-18.415
M3 3D STEP Top:
  text ".Layer_Name" at 11.306,-30.061 h1.52
M4 3D STEP Bottom:
  text ".Layer_Name" at 11.306,-30.061 h1.52
M5 Assembly Top:
  lines w0.254: -10.767,-31.881 156.873,-31.881 ; -10.767,-26.717 156.924,-26.717 ; -10.767,-21.552 -10.767,-37.046 90.96,-37.046 156.924,-37.046 156.924,-21.552 -10.754,-21.552 -10.754,-37.046 29.264,-37.046 ; 51.844,-37.046 51.844,-21.552 ; 84.026,-26.717 84.026,-21.552 ; 105.362,-26.717 105.362,-21.552 ; 121.161,-37.211 121.161,-32.059
  text "COMPONENTS MARKED 'DNP' SHOULD NOT BE POPULATED." at 25.949,-16.345 h0.64
  text "ASSEMBLY VARIANT:" at 25.936,-19.279 h0.64
  text ".VariantName" at 52.251,-19.279 h0.64
  text "PCB VIEWED FROM TOP SIDE" at -9.154,-24.909 h0.64
  text "BOARD #:" at 53.749,-24.909 h0.64
  text ".PRJ_Number" at 67.605,-24.909 h0.64
  text "REV:" at 89.055,-24.909 h0.64
  text ".PCB_Rev" at 96.459,-24.909 h0.64
  text "SVN REV:" at 110.34,-24.909 h0.64
  text ".VersionControl_RevNumber" at 123.193,-24.909 h0.64
  text "'.Layer_Name'" at 0.813,-29.947 h0.64
  text "LAYER NAME =" at -9.154,-30.061 h0.64
  text "TID #:" at 53.749,-30.074 h0.64
  text ".TID" at 67.605,-30.074 h0.64
  text "PLOT NAME =" at -9.154,-35.289 h0.64
  text ".plot_File_Name" at 11.306,-35.289 h0.64
  text "GENERATED    :" at 53.8,-35.289 h0.64
  text ".Print_Date" at 75.885,-35.289 h0.64
  text ".Print_Time" at 94.402,-35.289 h0.64
  text "TEXAS INSTRUMENTS" at 126.52,-35.289 h0.64
M6 Assembly Bottom:
  lines w0.254: -10.78,-26.729 156.911,-26.729 ; -10.729,-31.894 156.911,-31.894 ; 24.984,-37.224 24.984,-32.072 ; 40.782,-26.729 40.782,-21.565 ; 62.118,-26.729 62.118,-21.565 ; 94.3,-37.059 94.3,-21.565 ; 116.881,-37.059 156.899,-37.059 156.899,-21.565 -10.78,-21.565 -10.78,-37.059 55.184,-37.059 156.911,-37.059 156.911,-21.565
  text "COMPONENTS MARKED 'DNP' SHOULD NOT BE POPULATED." at 151.641,-16.332 h0.64
  text ".VariantName" at 125.123,-19.279 h0.64
  text "ASSEMBLY VARIANT:" at 151.514,-19.279 h0.64
  text ".VersionControl_RevNumber" at 22.952,-24.922 h0.64
  text "SVN REV:" at 35.804,-24.922 h0.64
  text ".PCB_Rev" at 49.685,-24.922 h0.64
  text "REV:" at 57.089,-24.922 h0.64
  text ".PRJ_Number" at 78.54,-24.922 h0.64
  text "BOARD #:" at 92.395,-24.922 h0.64
  text "PCB VIEWED FROM BOTTOM SIDE" at 155.298,-24.922 h0.64
  text "'.Layer_Name'" at 146.634,-29.337 h0.64
  text "LAYER NAME =" at 154.981,-29.477 h0.64
  text ".TID" at 78.54,-30.086 h0.64
  text "TID #:" at 92.395,-30.086 h0.64
  text "TEXAS INSTRUMENTS" at 19.624,-35.302 h0.64
  text ".Print_Time" at 51.743,-35.302 h0.64
  text ".Print_Date" at 70.259,-35.302 h0.64
  text "GENERATED    :" at 92.344,-35.302 h0.64
  text ".plot_File_Name" at 134.839,-35.302 h0.64
  text "PLOT NAME =" at 155.298,-35.302 h0.64
M9 Title Sheet:
  drawing of 57 lines, arcs and shapes, not listed
  text "1" at 15.442,195.872 h1.78
  text "2" at 78.832,195.872 h1.78
  text "3" at 142.061,195.872 h1.78
  text "4" at 205.73,195.872 h1.78
  text "5" at 269.205,195.872 h1.78
  text "6" at 332.832,195.872 h1.78
  text "A" at -13.929,166.84 h1.78
  text "A" at 361.991,166.84 h1.78
  text "B" at -13.929,106.388 h1.78
  text "B" at 361.991,106.388 h1.78
  text "C" at -13.929,46.063 h1.78
  text "C" at 361.991,46.063 h1.78
  text "PROJECT TITLE:" at 284.775,-1.206 h1.14
  text ".PRJ_Title" at 286.045,-4.593 h1.78
  text "DESIGNED FOR:" at 284.775,-8.852 h1.14
  text ".PRJ_Customer" at 286.045,-12.408 h1.78
  text "D" at -13.929,-14.135 h1.78
  text "D" at 361.991,-14.135 h1.78
  text "FILE NAME:" at 284.775,-16.472 h1.14
  text ".PCB_File_Name_No_Path" at 286.045,-19.52 h1.78
  text "Texas Instruments (TI) and/or its licensors do not warrant the accuracy or completeness of this specification" at 158.55,-23.631 h1.14
  text "ENGINEER:" at 284.775,-23.838 h1.14
  text "LAYOUT BY:" at 323.002,-23.838 h1.14
  text "or any information contained therein. TI and/or its licensors do not warrant that this design will meet" at 157.407,-26.492 h1.14
  text ".PRJ_Engineer" at 286.045,-27.775 h1.78
  text ".PCB_Layout" at 324.285,-27.775 h1.78
  text "the specifications, will be suitable for your application or fit for any particular purpose, or will operate in" at 157.407,-29.354 h1.14
  text "ALTIUM DESIGNER VERSION:" at 323.002,-31.712 h1.14
  text "an implementation. TI and/or its licensors do not warrant that the design is production worthy. You should" at 157.407,-32.216 h1.14
  text "completely validate and test your design implementation to confirm the system functionality for your application." at 158.55,-35.077 h1.14
  text ".print_Scale" at 286.045,-35.098 h1.78
  text ".Application_BuildNumber" at 324.285,-35.098 h1.78
  text "1" at 15.442,-40.348 h1.78
  text "2" at 78.832,-40.348 h1.78
  text "3" at 142.061,-40.348 h1.78
  text "4" at 205.73,-40.348 h1.78
  text "5" at 269.205,-40.348 h1.78
  text "6" at 332.832,-40.348 h1.78
M10 Fab Notes:
  drawing of 228 lines, arcs and shapes, not listed
  text "DESIGN INFORMATION" at 311.176,165.329 h1.52
  text "(REFER ALSO ARRAY/PANEL PROFILING INFORMATION)" at 301.993,161.222 h1.52
  text "BOARD SIZE" at 284.568,161.113 h1.52
  text "130MM" at 296.311,157.866 h1.52
  text "X" at 309.155,157.866 h1.52
  text "40MM" at 315.031,157.866 h1.52
  text "Number of Layers :" at 294.804,152.858 h1.52
  text "4" at 322.613,152.604 h1.52
  text "10" at 322.075,149.377 h1.52
  text "MIN. TRACK WIDTH:" at 294.804,149.327 h1.52
  text "MIL" at 326.58,149.327 h1.52
  text "MIL" at 326.596,146.355 h1.52
  text "7.7" at 321.211,146.177 h1.52
  text "MIN. CLEARANCE:" at 294.804,145.975 h1.52
  text "19.685" at 317.985,142.977 h1.52
  text "MIL" at 326.672,142.951 h1.52
  text "MIN. VIA DRILL SIZE:" at 294.804,142.622 h1.52
  text "MINIMUM ANNULAR RING" at 286.442,138.914 h1.52
  text "EXTERNAL" at 330.441,138.914 h1.52
  text "5.90 MIL" at 312.956,138.862 h1.52
  text "PER" at 291.522,135.916 h1.52
  text "IPC-D-275 CLASS 2 LEVEL C" at 297.11,135.916 h1.52
  text "MIL, HOLES" at 334.911,133.064 h1.52
  text "+/-" at 324.942,133.046 h1.52
  text "+/-" at 346.634,133.046 h1.52
  text "REGISTRATION TOLERANCES:" at 286.442,132.919 h1.52
  text "METAL" at 316.916,132.919 h1.52
  text "5" at 331.552,132.919 h1.52
  text "3" at 352.71,132.919 h1.52
  text "MIL" at 355.663,132.919 h1.52
  text "MATERIAL:" at 284.543,127.599 h1.52
  text "FR-4 High Tg" at 309.598,124.034 h1.52
  text "FR-408" at 295.236,123.817 h1.52
  text "X" at 305.562,123.826 h1.52
  text "OTHER" at 333.031,123.817 h1.52
  text "63 MIL (1.6mm) +/-10%" at 303.367,119.684 h1.52
  text "THICKNESS:" at 286.442,119.575 h1.52
  text "X" at 300.111,119.575 h1.52
  text "OTHER" at 336.003,119.575 h1.52
  text "TOLERANCE:" at 286.442,115.562 h1.52
  text "X" at 307.76,115.562 h1.52
  text "ANSI IPC-6012 TYPE 3 CLASS 2" at 312.509,115.562 h1.52
  text "OTHER +/-" at 312.508,111.599 h1.52
  text "BOW & TWIST:" at 286.442,107.611 h1.52
  text "X" at 307.76,107.611 h1.52
  text "ANSI IPC-6012 TYPE 3 CLASS 2" at 312.509,107.611 h1.52
  text "OTHER +/-" at 312.508,103.585 h1.52
  text "COPPER THICKNESS (FINISHED):" at 284.543,100.144 h1.52
  text "1.4MIL (1oz)" at 306.895,96.265 h1.52
  text "2MIL (1.4oz)" at 326.377,96.265 h1.52
  text "2.8MIL (2oz)" at 344.842,96.265 h1.52
  text "X" at 303.708,96.191 h1.52
  text "OUTER:" at 293.611,96.156 h1.52
  text "1.4MIL (1oz)" at 306.895,92.277 h1.52
  text "2.8MIL (2oz)" at 326.377,92.277 h1.52
  text "N/A" at 344.831,92.286 h1.52
  text "X" at 303.556,92.228 h1.52
  text "INNER SIGNAL:" at 286.268,92.168 h1.52
  text "DRILLING:" at 284.543,88.638 h1.52
  text "REFERENCE:" at 286.442,85.666 h1.52
  text "X" at 302.907,85.666 h1.52
  text "AS SHOWN" at 307.657,85.666 h1.52
  text "X" at 325.792,85.666 h1.52
  text "NC_DRILL FILES" at 329.272,85.666 h1.52
  text "PTH MIN COPPER THICKNESS:" at 286.442,81.653 h1.52
  text "X" at 320.738,81.653 h1.52
  text "1MIL" at 324.218,81.653 h1.52
  text "OTHER" at 336.841,81.653 h1.52
  text "BOARD FINISH:" at 284.543,77.614 h1.52
  text "SILKSCREEN:" at 288.485,74.617 h1.52
  text "X" at 312.584,74.617 h1.52
  text "TOP" at 315.785,74.617 h1.52
  text "BOTTOM" at 328.764,74.617 h1.52
  text "X" at 325.513,74.591 h1.52
  text "SILKSCREEN COLOR:" at 288.485,70.375 h1.52
  text "X" at 312.558,70.375 h1.52
  text "WHITE" at 315.785,70.375 h1.52
  text "OTHER" at 328.764,70.375 h1.52
  text "SOLDER RESIST COLOR:" at 288.485,66.057 h1.52
  text "X" at 302.906,62.013 h1.52
  text "GREEN" at 306.133,62.013 h1.52
  text "BLUE" at 321.144,62.013 h1.52
  text "OTHER" at 334.809,62.013 h1.52
  text "IMMERSION GOLD (ENIG)" at 311.492,57.225 h1.52
  text "ENEPIG" at 345.466,57.142 h1.52
  text "SURFACE FINISH:" at 284.543,57.116 h1.52
  text "X" at 306.744,57.116 h1.52
  text "IMM. TIN/SILVER OR EQUIV" at 292.913,53.128 h1.52
  text "OTHER" at 329.272,53.128 h1.52
  text "ARRAY/PANEL:" at 284.543,48.582 h1.52
  text "CUT AND TRIM PER MECH LAYER 1" at 311.492,48.473 h1.52
  text "X" at 328.561,44.721 h1.52
  text "N.C. ROUTE" at 311.492,44.619 h1.52
  text "V. SCORE" at 333.489,44.619 h1.52
  text "CERTIFICATION:" at 284.543,41.14 h1.52
  text "MATERIALS AND WORKMANSHIP FOR ALL PCBS" at 302.958,41.14 h1.52
  text "TO MEET OR EXCEED THE REQUIREMENTS OF:" at 302.958,38.65 h1.52
  text "X" at 293.471,35.183 h1.52
  text "ANSI IPC-A-600F CLASS ->" at 297.002,35.183 h1.52
  text "X" at 338.634,35.183 h1.52
  text "2" at 341.655,35.183 h1.52
  text "1" at 333.654,35.145 h1.52
  text "3" at 350.646,35.145 h1.52
  text "X" at 293.523,31.132 h1.52
  text "UL 94V-0" at 297.002,31.132 h1.52
  text "X" at 314.148,31.132 h1.52
  text "RoHS" at 317.626,31.132 h1.52
  text "OTHER" at 333.994,31.132 h1.52
  text "PER ORDER" at 344.079,31.132 h1.52
  text "VIA TENTING:" at 315.468,27.738 h1.52
  text "ADDITIONAL REQUIREMENTS:" at 284.543,27.551 h1.52
  text "X" at 343.052,27.534 h1.52
  text "YES" at 329.43,27.507 h1.52
  text "NO" at 338.696,27.374 h1.52
  text "MICROSECTION:" at 286.442,24.63 h1.52
  text "YES" at 309.448,24.63 h1.52
  text "IMPEDANCE CONTROL:" at 316.027,24.461 h1.52
  text "YES" at 341.021,24.436 h1.52
  text "X" at 354.714,24.105 h1.52
  text "NO" at 350.558,23.996 h1.52
  text "REQUIRED" at 331.33,20.664 h1.52
  text "BARE BOARD ELEC. TEST:" at 286.442,20.591 h1.52
  text "NONE" at 319.608,20.591 h1.52
  text "X" at 328.104,20.591 h1.52
  text "PER ORDER" at 346.366,20.591 h1.52
  text "MANUFACTURER'S UL:" at 286.442,16.603 h1.52
  text "RAIL" at 316.052,16.494 h1.52
  text "METAL" at 328.544,16.494 h1.52
  text "X" at 338.074,16.485 h1.52
  text "SILK" at 341.54,16.494 h1.52
M11 Gerber Information:
  lines w0.254: -10.767,-31.881 156.873,-31.881 ; -10.767,-26.717 156.924,-26.717 ; -10.767,-21.552 -10.767,-37.046 90.96,-37.046 156.924,-37.046 156.924,-21.552 -10.754,-21.552 -10.754,-37.046 29.264,-37.046 ; 51.844,-37.046 51.844,-21.552 ; 84.026,-26.717 84.026,-21.552 ; 105.362,-26.717 105.362,-21.552 ; 121.161,-37.211 121.161,-32.059
  text "ALL ARTWORK VIEWED FROM TOP SIDE" at -9.154,-24.909 h1.52
  text "BOARD #:" at 53.749,-24.909 h1.52
  text ".PRJ_Number" at 67.605,-24.909 h0.76
  text "REV:" at 89.055,-24.909 h1.52
  text ".PCB_Rev" at 96.459,-24.909 h1.52
  text "SVN REV:" at 110.34,-24.909 h1.52
  text ".VersionControl_RevNumber" at 123.193,-24.909 h1.52
  text "LAYER NAME =" at -9.281,-30.035 h1.52
  text "TID #:" at 53.749,-30.074 h1.52
  text ".TID" at 67.605,-30.074 h1.52
  text "PLOT NAME =" at -9.154,-35.289 h1.52
  text ".plot_File_Name" at 11.306,-35.289 h0.76
  text "GENERATED    :" at 53.8,-35.289 h1.52
  text ".Print_Date" at 75.885,-35.289 h1.52
  text ".Print_Time" at 94.402,-35.289 h1.52
  text "TEXAS INSTRUMENTS" at 126.52,-35.289 h1.52
M12 Stackup:
  drawing of 295 lines, arcs and shapes, not listed
  text "Layer" at 156.248,182.334 h1.52
  text "Name" at 166.66,182.334 h1.52
  text "Material" at 190.275,182.334 h1.52
  text "Thickness" at 212.113,182.334 h1.52
  text "Constant" at 228.619,182.334 h1.52
  text "Board Layer Stack" at 243.094,182.334 h1.52
  text "Top Overlay" at 166.66,179.286 h1.52
  text "Top Solder" at 166.66,176.238 h1.52
  text "Solder Resist" at 190.275,176.238 h1.52
  text "0.40mil" at 212.113,176.238 h1.52
  text "3.5" at 228.619,176.238 h1.52
  text "1" at 156.248,173.19 h1.52
  text "Top Layer" at 166.66,173.19 h1.52
  text "1.40mil" at 212.113,173.19 h1.52
  text "Dielectric1" at 166.66,170.142 h1.52
  text "FR-4 High Tg" at 190.275,170.142 h1.52
  text "22.00mil" at 212.113,170.142 h1.52
  text "4.2" at 228.619,170.142 h1.52
  text "2" at 156.248,167.094 h1.52
  text "GND" at 166.66,167.094 h1.52
  text "1.40mil" at 212.113,167.094 h1.52
  text "Dielectric 2" at 166.66,164.046 h1.52
  text "FR-4 High Tg" at 190.275,164.046 h1.52
  text "13.00mil" at 212.113,164.046 h1.52
  text "4.2" at 228.619,164.046 h1.52
  text "3" at 156.248,160.998 h1.52
  text "PWR" at 166.66,160.998 h1.52
  text "1.40mil" at 212.113,160.998 h1.52
  text "Dielectric 3" at 166.66,157.95 h1.52
  text "FR-4 High Tg" at 190.275,157.95 h1.52
  text "22.00mil" at 212.113,157.95 h1.52
  text "4.2" at 228.619,157.95 h1.52
  text "4" at 156.248,154.902 h1.52
  text "Bottom Layer" at 166.66,154.902 h1.52
  text "1.40mil" at 212.113,154.902 h1.52
  text "Bottom Solder" at 166.66,151.854 h1.52
  text "Solder Resist" at 190.275,151.854 h1.52
  text "0.40mil" at 212.113,151.854 h1.52
  text "3.5" at 228.619,151.854 h1.52
  text "Bottom Overlay" at 166.66,148.806 h1.52
M13 Component Bodies Top:
  text ".Layer_Name" at 11.306,-30.061 h1.52
M14 Component Bodies Bottom:
  text ".Layer_Name" at 11.306,-30.061 h1.52
M15 Courtyards Top:
  text ".Layer_Name" at 11.306,-30.061 h1.52
M16 Courtyards Bottom:
  text ".Layer_Name" at 11.306,-30.061 h1.52
Drill Drawing:
  text "FOR 7.874MIL DRILL +0/-7.874MIL" at 229.25,45.75 h1.52
  text "FOR 12MIL DRILL +0/-12MIL" at 230.093,41.473 h1.52
  text "FOR PTH DRILL +/-3MIL" at 230.093,39.085 h1.52
  text "FOR NPTH DRILL +/-2MIL" at 230.093,36.723 h1.52
  text ".Layer_Name" at 11.306,-30.061 h1.52
M17 Embedded Cavity:
  text ".Layer_Name" at 11.306,-30.061 h1.52
M18 Embedded Assembly:
  text ".Layer_Name" at 11.306,-30.061 h1.52
M19 Embedded Keepout:
  text ".Layer_Name" at 11.306,-30.061 h1.52

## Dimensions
-3.35,-18.415 to 22.05,-18.415 on M2 Board Dimensions
0,43 to 135,43 on M2 Board Dimensions
0,0 to 0,43 on M2 Board Dimensions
